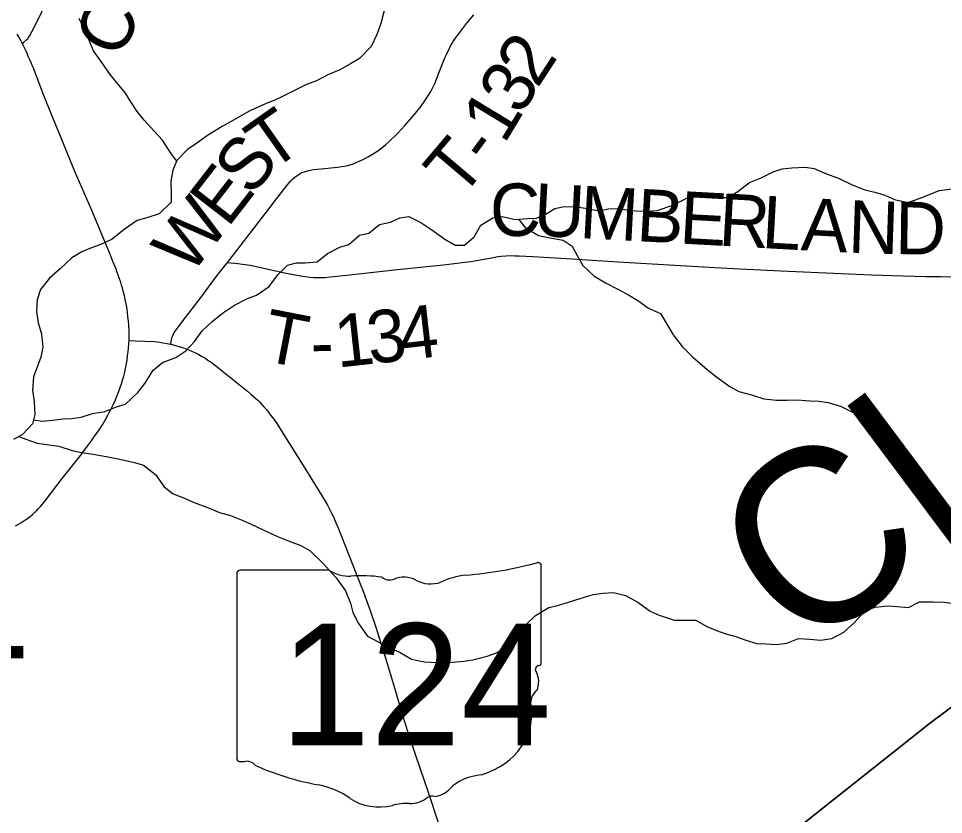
# Model space of a CAD drawing. Extents: x 0 to 1052, y -194 to 246.
# Drawn here: x 4.503 to 5.505, y 17.846 to 18.708 of the extents above; entities that cross this region are included whole.
import ezdxf

# ---------------------------------------------------------------- set-up
doc = ezdxf.new("R2010")
doc.units = 0
for name, color, linetype in [('GM_X_Corporation', 7, 'Continuous'), ('GM_X_County_Road', 7, 'Continuous'), ('GM_X_County_Road_Text', 7, 'Continuous'), ('GM_X_County_Text', 7, 'Continuous'), ('GM_X_Major_River', 7, 'Continuous'), ('GM_X_Minor_River', 7, 'Continuous'), ('GM_X_State_Location', 7, 'Continuous'), ('GM_X_State_Route', 7, 'Continuous'), ('GM_X_State_Shield', 7, 'Continuous'), ('GM_X_Township_Road', 7, 'Continuous'), ('GM_X_Township_Road_Text', 7, 'Continuous')]:
    doc.layers.add(name, color=color, linetype=linetype)

msp = doc.modelspace()

# ---------------------------------------------------------------- linework, layer by layer
at = {"layer": 'GM_X_Corporation'}
for points in [[(5.1788, 17.6981), (5.491, 17.9457), (6.1888, 18.4644), (6.5994, 18.7694), (6.8785, 18.9763), (8.1871, 19.9814), (8.6571, 20.341), (8.7822, 20.435), (8.7822, 21.0055), (1.9822, 21.0055), (1.9822, 14.2055)], [(5.1788, 17.6981), (5.491, 17.9457), (6.1888, 18.4644), (6.152, 18.6129), (5.992, 19.3448), (5.9283, 19.6076), (5.6935, 20.5776), (5.5898, 21.0055), (1.9822, 21.0055), (1.9822, 14.2055)], [(8.7822, 14.2055), (8.7822, 20.435), (8.6571, 20.341), (8.1871, 19.9814), (6.8785, 18.9763), (6.5994, 18.7694), (6.1888, 18.4644), (5.491, 17.9457), (5.1788, 17.6981)], [(8.7822, 14.2055), (8.7822, 19.8853), (8.7716, 19.9458), (8.7665, 19.9791), (8.7595, 20.0343), (8.7564, 20.0663), (8.7504, 20.1046), (8.7444, 20.1332), (8.7375, 20.1583), (8.7292, 20.1831), (8.7137, 20.2216), (8.6781, 20.298), (8.6571, 20.341), (8.1871, 19.9814), (6.8785, 18.9763), (6.5994, 18.7694), (6.1888, 18.4644), (5.491, 17.9457), (5.1788, 17.6981)]]:
    msp.add_lwpolyline(points, dxfattribs=at)
at = {"layer": 'GM_X_County_Road'}
msp.add_lwpolyline([(4.5076, 18.6802), (4.5092, 18.6818), (4.5122, 18.6847), (4.5132, 18.6857), (4.5142, 18.6871), (4.5155, 18.6892), (4.5179, 18.6937), (4.5205, 18.6985), (4.5365, 18.7315)], dxfattribs=at)
at = {"layer": 'GM_X_Major_River'}
for points in [[(4.9006, 18.7216), (4.8956, 18.702), (4.8912, 18.6903), (4.8849, 18.6771), (4.8725, 18.6641), (4.8625, 18.6586), (4.8513, 18.652), (4.8383, 18.6466), (4.826, 18.64), (4.8149, 18.636), (4.8, 18.6287), (4.7904, 18.624), (4.7808, 18.6193), (4.7712, 18.6157), (4.7528, 18.6073), (4.7386, 18.5989), (4.7237, 18.5908), (4.709, 18.5816), (4.6963, 18.5728), (4.6863, 18.5658), (4.6747, 18.5539), (4.6703, 18.5433), (4.6681, 18.5316), (4.6686, 18.5183), (4.6684, 18.5088), (4.6556, 18.4962), (4.6422, 18.4919), (4.6319, 18.4891), (4.6177, 18.4791), (4.6046, 18.4687), (4.5923, 18.4629), (4.5823, 18.4593), (4.572, 18.455), (4.5609, 18.4484), (4.5485, 18.4365), (4.5369, 18.4265), (4.5271, 18.4141), (4.5235, 18.4032), (4.5228, 18.3903), (4.5245, 18.3781), (4.528, 18.3663), (4.5296, 18.3519), (4.5275, 18.3409), (4.5194, 18.3198), (4.5184, 18.3054), (4.5204, 18.2925), (4.5208, 18.2788), (4.5184, 18.269), (4.5075, 18.2574)], [(4.5075, 18.2574), (4.4979, 18.2519)]]:
    msp.add_lwpolyline(points, dxfattribs=at)
at = {"layer": 'GM_X_Minor_River'}
for points in [[(4.6745, 18.5533), (4.6683, 18.5617), (4.659, 18.5758), (4.6504, 18.5854), (4.6392, 18.5974), (4.6317, 18.6069), (4.625, 18.6173), (4.6191, 18.6269), (4.6105, 18.6372), (4.6026, 18.6468), (4.5926, 18.661), (4.5844, 18.6725), (4.5792, 18.6855), (4.5752, 18.695), (4.5689, 18.7076)], [(4.5194, 18.2732), (4.5292, 18.2719), (4.5402, 18.2729), (4.5513, 18.2743), (4.5608, 18.2746), (4.5711, 18.2759), (4.5833, 18.28), (4.5966, 18.2821), (4.6092, 18.2872), (4.6191, 18.2901), (4.6326, 18.3029), (4.6399, 18.3126), (4.6492, 18.3269), (4.6592, 18.3352), (4.6737, 18.3407), (4.6845, 18.3477), (4.6937, 18.3579), (4.7022, 18.3695), (4.713, 18.3796), (4.7253, 18.3893), (4.7372, 18.3972), (4.7513, 18.4046), (4.7608, 18.4082), (4.7746, 18.4176), (4.7839, 18.4303), (4.7943, 18.4405), (4.8042, 18.443), (4.8137, 18.4432), (4.8267, 18.4442), (4.8378, 18.4532), (4.8512, 18.4602), (4.8607, 18.4631), (4.8723, 18.4732), (4.8825, 18.4754), (4.8941, 18.4847), (4.9059, 18.4872), (4.9162, 18.4917), (4.9257, 18.4934), (4.9389, 18.4868), (4.9506, 18.4787), (4.9649, 18.4686), (4.9758, 18.4624), (4.9861, 18.4623), (4.9964, 18.4712), (5.0038, 18.4837), (5.0168, 18.4919), (5.0267, 18.4933), (5.0411, 18.49), (5.0541, 18.491), (5.0639, 18.4916), (5.0735, 18.4953), (5.0838, 18.502), (5.0941, 18.5042), (5.107, 18.5036), (5.1169, 18.5023), (5.1317, 18.4995), (5.1419, 18.5016), (5.1522, 18.5019), (5.1617, 18.5006), (5.1719, 18.4993), (5.1841, 18.4992), (5.1947, 18.4998), (5.2115, 18.5057), (5.2226, 18.5108), (5.2344, 18.5168), (5.2451, 18.517), (5.2576, 18.5138), (5.2712, 18.514), (5.282, 18.5203), (5.2946, 18.53), (5.3072, 18.5352), (5.3202, 18.5415), (5.3298, 18.5448), (5.3404, 18.5458), (5.3549, 18.5467), (5.3647, 18.5451), (5.376, 18.54), (5.3915, 18.5345), (5.4059, 18.5274), (5.4195, 18.5223), (5.4301, 18.5195), (5.4411, 18.5164), (5.4516, 18.5117), (5.466, 18.5084), (5.4794, 18.5132), (5.4893, 18.5169), (5.4999, 18.5214)], [(5.4999, 18.5214), (5.5142, 18.5231)], [(5.0445, 18.4903), (5.0516, 18.4815), (5.0663, 18.4726), (5.0807, 18.4698), (5.0929, 18.4677), (5.1026, 18.4611), (5.1082, 18.4512), (5.1141, 18.4401), (5.1261, 18.4289), (5.1386, 18.4216), (5.1514, 18.415), (5.1646, 18.4079), (5.1748, 18.4017), (5.1853, 18.394), (5.1981, 18.3882), (5.2063, 18.3748), (5.2119, 18.3652), (5.2216, 18.3525), (5.2328, 18.3414), (5.2486, 18.3275), (5.2591, 18.3194), (5.2734, 18.3094), (5.2832, 18.3039), (5.2969, 18.3003), (5.3101, 18.296), (5.3237, 18.2943), (5.3355, 18.2945), (5.3462, 18.2947), (5.3598, 18.2938), (5.3701, 18.2933), (5.3796, 18.292), (5.3932, 18.2881), (5.4068, 18.2811), (5.4189, 18.2782)], [(4.5037, 18.2553), (4.5111, 18.2524), (4.5236, 18.2481), (4.5338, 18.2464), (4.5471, 18.2447), (4.5615, 18.24), (4.5713, 18.238), (4.5842, 18.2359), (4.5982, 18.2334), (4.6111, 18.231), (4.6289, 18.227), (4.6387, 18.2242), (4.6515, 18.2142), (4.6608, 18.2007), (4.6706, 18.193), (4.6812, 18.1891), (4.6936, 18.1836), (4.7106, 18.1773), (4.7208, 18.173), (4.7326, 18.1698), (4.7454, 18.1647), (4.7552, 18.1604), (4.7681, 18.1542), (4.7835, 18.1468), (4.7964, 18.142), (4.8089, 18.1373), (4.819, 18.1315), (4.8333, 18.1173), (4.8471, 18.1023), (4.8572, 18.0881), (4.8627, 18.0748), (4.8652, 18.0648), (4.8712, 18.0526), (4.8812, 18.0392), (4.8941, 18.0322), (4.9061, 18.026), (4.9163, 18.0213), (4.9288, 18.0143), (4.9424, 18.0111), (4.9568, 18.0105), (4.969, 18.0107), (4.9853, 18.012), (4.9952, 18.0134), (5.0105, 18.0174), (5.0208, 18.0211), (5.0315, 18.027), (5.0404, 18.0394), (5.0527, 18.0518), (5.0631, 18.0615), (5.0773, 18.0701), (5.0868, 18.0722), (5.0986, 18.0759), (5.1112, 18.0799), (5.1253, 18.0843), (5.1363, 18.0856), (5.1474, 18.0862), (5.1602, 18.083), (5.1738, 18.076), (5.187, 18.066), (5.1968, 18.0617), (5.2131, 18.0562), (5.2256, 18.0564), (5.2366, 18.0562), (5.2483, 18.0496), (5.2589, 18.0453), (5.2691, 18.0414), (5.2797, 18.0386), (5.2906, 18.0347), (5.3027, 18.0311), (5.313, 18.0306), (5.3236, 18.0301), (5.335, 18.0314), (5.3476, 18.0366), (5.3594, 18.0357), (5.3715, 18.0348), (5.3837, 18.0365), (5.3967, 18.0435), (5.4075, 18.0533), (5.4202, 18.0668), (5.4305, 18.0704), (5.4446, 18.0718), (5.4544, 18.0713), (5.4666, 18.07), (5.4788, 18.0763), (5.4937, 18.0762)], [(5.4937, 18.0762), (5.5052, 18.0757), (5.5181, 18.074), (5.5279, 18.0751), (5.5408, 18.0757), (5.5518, 18.076), (5.5647, 18.0755), (5.5776, 18.0743), (5.5898, 18.0745)]]:
    msp.add_lwpolyline(points, dxfattribs=at)
at = {"layer": 'GM_X_State_Route'}
for points in [[(4.5818, 18.5014), (4.5643, 18.542), (4.5476, 18.5828), (4.5391, 18.6035), (4.5301, 18.626), (4.5194, 18.6538), (4.5185, 18.656), (4.5173, 18.6588), (4.5156, 18.6629), (4.5139, 18.6666), (4.5125, 18.6697), (4.5111, 18.673), (4.5097, 18.6759), (4.5076, 18.6802), (4.5059, 18.6836), (4.504, 18.6871), (4.502, 18.6907)], [(4.521, 18.173), (4.5224, 18.1744), (4.5246, 18.1768), (4.527, 18.1794), (4.5321, 18.1856), (4.5506, 18.2098), (4.5707, 18.2351), (4.5735, 18.2389), (4.5775, 18.2442), (4.5807, 18.2485), (4.583, 18.2517), (4.5857, 18.2555), (4.589, 18.2601), (4.5919, 18.2645), (4.5941, 18.2679), (4.5961, 18.2712), (4.5976, 18.2737), (4.6001, 18.2784), (4.6022, 18.2825), (4.6037, 18.2852), (4.6058, 18.2896), (4.6082, 18.2947), (4.6099, 18.2988), (4.6117, 18.3033), (4.6135, 18.3082), (4.6148, 18.312), (4.616, 18.3163), (4.6172, 18.3203), (4.6183, 18.3249), (4.6192, 18.3287), (4.6202, 18.3341), (4.6208, 18.3379), (4.6214, 18.3424), (4.622, 18.3471), (4.6224, 18.3509), (4.6228, 18.3557), (4.6229, 18.3589), (4.6229, 18.3601), (4.6231, 18.3637), (4.623, 18.3676), (4.623, 18.3705), (4.6228, 18.3734), (4.6226, 18.3759), (4.6224, 18.3798), (4.6218, 18.3852), (4.6213, 18.3896), (4.6208, 18.3925), (4.6204, 18.395), (4.6198, 18.3987), (4.6188, 18.4035), (4.6179, 18.4078), (4.6167, 18.4124), (4.6157, 18.4162), (4.6148, 18.4188), (4.6139, 18.4218), (4.6123, 18.4268), (4.6112, 18.4298), (4.6101, 18.4328), (4.6085, 18.4373), (4.607, 18.4412), (4.6058, 18.444), (4.6041, 18.4485), (4.6029, 18.4515), (4.5818, 18.5014)], [(4.6229, 18.3589), (4.6301, 18.3586), (4.6506, 18.3578), (4.6534, 18.3575), (4.6562, 18.3572), (4.6594, 18.3567), (4.6623, 18.3562), (4.666, 18.3554), (4.6677, 18.355), (4.6697, 18.3546), (4.6734, 18.3536), (4.6769, 18.3526), (4.6807, 18.3513), (4.6846, 18.35), (4.6882, 18.3485), (4.6916, 18.3471), (4.6947, 18.3456), (4.6984, 18.3438), (4.7012, 18.3422), (4.7049, 18.3402), (4.7084, 18.3379), (4.7117, 18.3357), (4.7152, 18.333), (4.7183, 18.3306), (4.7206, 18.3288), (4.751, 18.3042), (4.7547, 18.3011)], [(4.7547, 18.3011), (4.7577, 18.2986), (4.76, 18.2965), (4.7623, 18.2943), (4.764, 18.2926), (4.7663, 18.2903), (4.7689, 18.2873), (4.7716, 18.2842), (4.7742, 18.2809), (4.7766, 18.2778), (4.7795, 18.2738), (4.7828, 18.2691), (4.7896, 18.2587), (4.8132, 18.2207), (4.8285, 18.1965), (4.8352, 18.1853), (4.8376, 18.1808), (4.8399, 18.1765), (4.8421, 18.1721), (4.8441, 18.1681), (4.8461, 18.1636), (4.8494, 18.1562), (4.8509, 18.1524), (4.8534, 18.1462), (4.8686, 18.1077), (4.8768, 18.0868), (4.884, 18.0669), (4.8902, 18.0487), (4.8956, 18.0314), (4.9001, 18.0166), (4.9102, 17.9833), (4.919, 17.9535), (4.9259, 17.9316), (4.9331, 17.9104), (4.947, 17.8692), (4.9575, 17.8373)], [(4.5, 18.1583), (4.5034, 18.1603), (4.5058, 18.1617), (4.5085, 18.1634), (4.5115, 18.1654), (4.5141, 18.1672), (4.5162, 18.1689), (4.5184, 18.1706), (4.5202, 18.1724), (4.521, 18.173)]]:
    msp.add_lwpolyline(points, dxfattribs=at)
at = {"layer": 'GM_X_State_Shield'}
for p, q in [((5.0692, 18.0106), (5.0692, 18.1153)), ((4.7397, 18.1069), (4.7397, 17.9068)), ((4.8394, 18.1104), (4.7429, 18.1104)), ((5.0692, 18.0107), (5.0692, 18.0106))]:
    msp.add_line(p, q, dxfattribs=at)
for centre, major_axis, start_param, end_param in [((4.9518, 18.3832), (0.3495, 0), 4.814394, 5.042369), ((5.0656, 18.1157), (0.00367, 0), 6.141152, 7.989035), ((4.7434, 18.1073), (0.00382, 0), 1.712693, 3.28349), ((4.8624, 18.1336), (0.037, 0), 4.042523, 4.731795), ((4.8747, 17.998), (0.133, 0), 1.404758, 1.657858), ((4.9964, 18.0492), (0.0703, 0), 1.699011, 2.107814), ((4.9049, 18.1084), (0.0107, 0), 3.836095, 5.185415), ((4.9206, 18.0852), (0.0222, 0), 0.950623, 2.079405), ((4.9492, 18.117), (0.0267, 0), 4.081561, 5.145723), ((5.0684, 18.0029), (0.00568, 0), 1.883978, 3.671073), ((5.0653, 18.0102), (0.00393, 0), 5.05454, 6.418171), ((5.0323, 17.9897), (0.0341, 0), 5.934695, 6.695948), ((5.0824, 17.9668), (0.0248, 0), 2.387724, 3.262537), ((4.9714, 17.9535), (0.0874, 0), 5.101752, 6.440018), ((4.7435, 17.9064), (0.00385, 0), 3.00124, 4.508301), ((4.7501, 17.8952), (0.0106, 0), 0.519207, 1.627899), ((4.744, 17.9268), (0.0294, 0), 4.665946, 4.897461), ((4.8839, 18.075), (0.2524, 0), 4.195997, 4.488961), ((5.0083, 17.8506), (0.0479, 0), 1.647645, 2.488434), ((4.8086, 17.8169), (0.079, 0), 0.823519, 1.323587), ((4.9476, 17.8874), (0.0282, 0), 4.937069, 5.64225), ((4.9267, 17.8793), (0.0267, 0), 4.691044, 5.507374), ((4.9508, 17.8599), (0.00752, 0), 1.147584, 2.315152), ((4.894, 17.8943), (0.0501, 0), 4.026481, 4.996735), ((4.923, 17.8251), (0.0412, 0), 1.495662, 1.94098)]:
    msp.add_ellipse(centre, major_axis=major_axis, ratio=0.8, start_param=start_param, end_param=end_param, dxfattribs=at)
at = {"layer": 'GM_X_Township_Road'}
for points in [[(4.7294, 18.4436), (4.7467, 18.4657), (4.7709, 18.4972), (4.7814, 18.511), (4.794, 18.5272), (4.7982, 18.532), (4.8002, 18.5339), (4.8023, 18.5359), (4.806, 18.5385), (4.8093, 18.5404), (4.8135, 18.542), (4.8177, 18.5431), (4.8227, 18.544), (4.8308, 18.5449), (4.845, 18.5462), (4.849, 18.5467), (4.853, 18.5472), (4.8562, 18.5477), (4.8596, 18.5486), (4.8633, 18.5497), (4.8666, 18.5508), (4.8697, 18.5521), (4.8729, 18.5534), (4.8758, 18.5545), (4.8789, 18.5564), (4.8817, 18.5579), (4.8848, 18.5597), (4.8882, 18.5618), (4.8911, 18.5637), (4.8937, 18.5655), (4.8971, 18.568), (4.9008, 18.5711), (4.9047, 18.5743), (4.9135, 18.583), (4.9215, 18.5916), (4.9316, 18.6034), (4.939, 18.6125), (4.9447, 18.6205), (4.9495, 18.6285), (4.9538, 18.6373), (4.9588, 18.6493), (4.9649, 18.6649), (4.9662, 18.6678), (4.9677, 18.6712), (4.9693, 18.6745), (4.9707, 18.6773), (4.9723, 18.68), (4.9738, 18.6827), (4.977, 18.6874), (4.9805, 18.692), (4.9849, 18.6978), (4.9884, 18.7022), (4.9923, 18.707), (4.9961, 18.7115)], [(4.7294, 18.4436), (4.7406, 18.4423), (4.7456, 18.4418), (4.7542, 18.4405), (4.7657, 18.4382), (4.7912, 18.4324), (4.8046, 18.4296), (4.8132, 18.4283), (4.8187, 18.4277), (4.8228, 18.4273), (4.8267, 18.4271), (4.8307, 18.4272), (4.8348, 18.4273), (4.8409, 18.4279), (4.8446, 18.4283), (4.8514, 18.4291), (4.8582, 18.4298), (4.8811, 18.4324), (4.9169, 18.4363), (4.9633, 18.441), (4.9836, 18.4433), (4.9929, 18.4446), (5.0014, 18.446), (5.0069, 18.4471), (5.0155, 18.4487), (5.0203, 18.4495), (5.0253, 18.4503), (5.0309, 18.4507), (5.0358, 18.4509), (5.0404, 18.4508), (5.0451, 18.4508), (5.06, 18.4499), (5.1022, 18.4475), (5.1524, 18.4442), (5.2076, 18.4409), (5.2386, 18.4392), (5.2572, 18.4382), (5.2845, 18.4367), (5.3285, 18.4343), (5.3937, 18.4314), (5.4266, 18.43), (5.4608, 18.4292), (5.4856, 18.4285), (5.5018, 18.4282), (5.5204, 18.4278)], [(4.6677, 18.355), (4.6684, 18.3577), (4.6694, 18.3618), (4.6702, 18.3641), (4.671, 18.3661), (4.672, 18.3679), (4.6806, 18.3794), (4.7009, 18.4061), (4.718, 18.429), (4.7294, 18.4436)]]:
    msp.add_lwpolyline(points, dxfattribs=at)

# ---------------------------------------------------------------- texts
at = {"layer": 'GM_X_County_Road_Text'}
msp.add_text('C-7', height=0.05682, rotation=64.0471, dxfattribs=at).set_placement((4.6127, 18.6623))
at = {"layer": 'GM_X_County_Text'}
msp.add_text('CLINTON COUNTY', height=0.189394, rotation=36.7754, dxfattribs=at).set_placement((5.3509, 18.0148))
at = {"layer": 'GM_X_State_Location'}
for s in ['s', 'r']:
    msp.add_text(s, height=0.000189, dxfattribs=at).set_placement((4.9007, 17.9935))
msp.add_text('124', height=0.000189, rotation=0, dxfattribs=at).set_placement((4.8339, 17.9798))
at = {"layer": 'GM_X_State_Shield'}
for s, p in [('134', (4.2195, 17.9851)), ('124', (4.7862, 17.9209))]:
    msp.add_text(s, height=0.13184, dxfattribs=at).set_placement(p)
at = {"layer": 'GM_X_Township_Road_Text'}
for s, rotation, p in [('2', 56.9161, (5.0649, 18.6311)), ('3', 59.8068, (5.0477, 18.6015)), ('1', 58.7932, (5.029, 18.5706)), ('T', 35.1546, (4.7761, 18.5408)), ('S', 51.9583, (4.7557, 18.5136)), ('T', 49.7297, (4.9819, 18.5115)), ('-', 53.4536, (5.0119, 18.547)), ('E', 52.2498, (4.7297, 18.4801)), ('C', 1.5496, (5.0144, 18.4714)), ('U', 356.9459, (5.0599, 18.4727)), ('M', 356.8677, (5.1098, 18.47)), ('W', 52.2619, (4.6894, 18.428)), ('B', 356.8643, (5.1714, 18.4667)), ('E', 356.8719, (5.218, 18.4641)), ('R', 356.8643, (5.2604, 18.4618)), ('L', 356.8719, (5.307, 18.4592)), ('A', 356.9901, (5.3496, 18.4569)), ('N', 358.1047, (5.4007, 18.4542)), ('D', 359.2924, (5.452, 18.4526)), ('4', 6.5196, (4.9183, 18.3374)), ('T', 349.0565, (4.7649, 18.3378)), ('1', 6.2797, (4.8485, 18.3296)), ('3', 6.4557, (4.8835, 18.3334)), ('-', 1.437, (4.82, 18.3286))]:
    msp.add_text(s, height=0.0568, rotation=rotation, dxfattribs=at).set_placement(p)

doc.saveas('drawing.dxf')
